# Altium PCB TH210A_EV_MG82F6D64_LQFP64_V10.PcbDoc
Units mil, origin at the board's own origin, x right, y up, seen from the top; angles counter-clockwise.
Board outline 3110.24 x 2110 mil, 2 copper layers (Top Layer, Bottom Layer); 48 components, 79 nets, 337 pads, 187 vias.
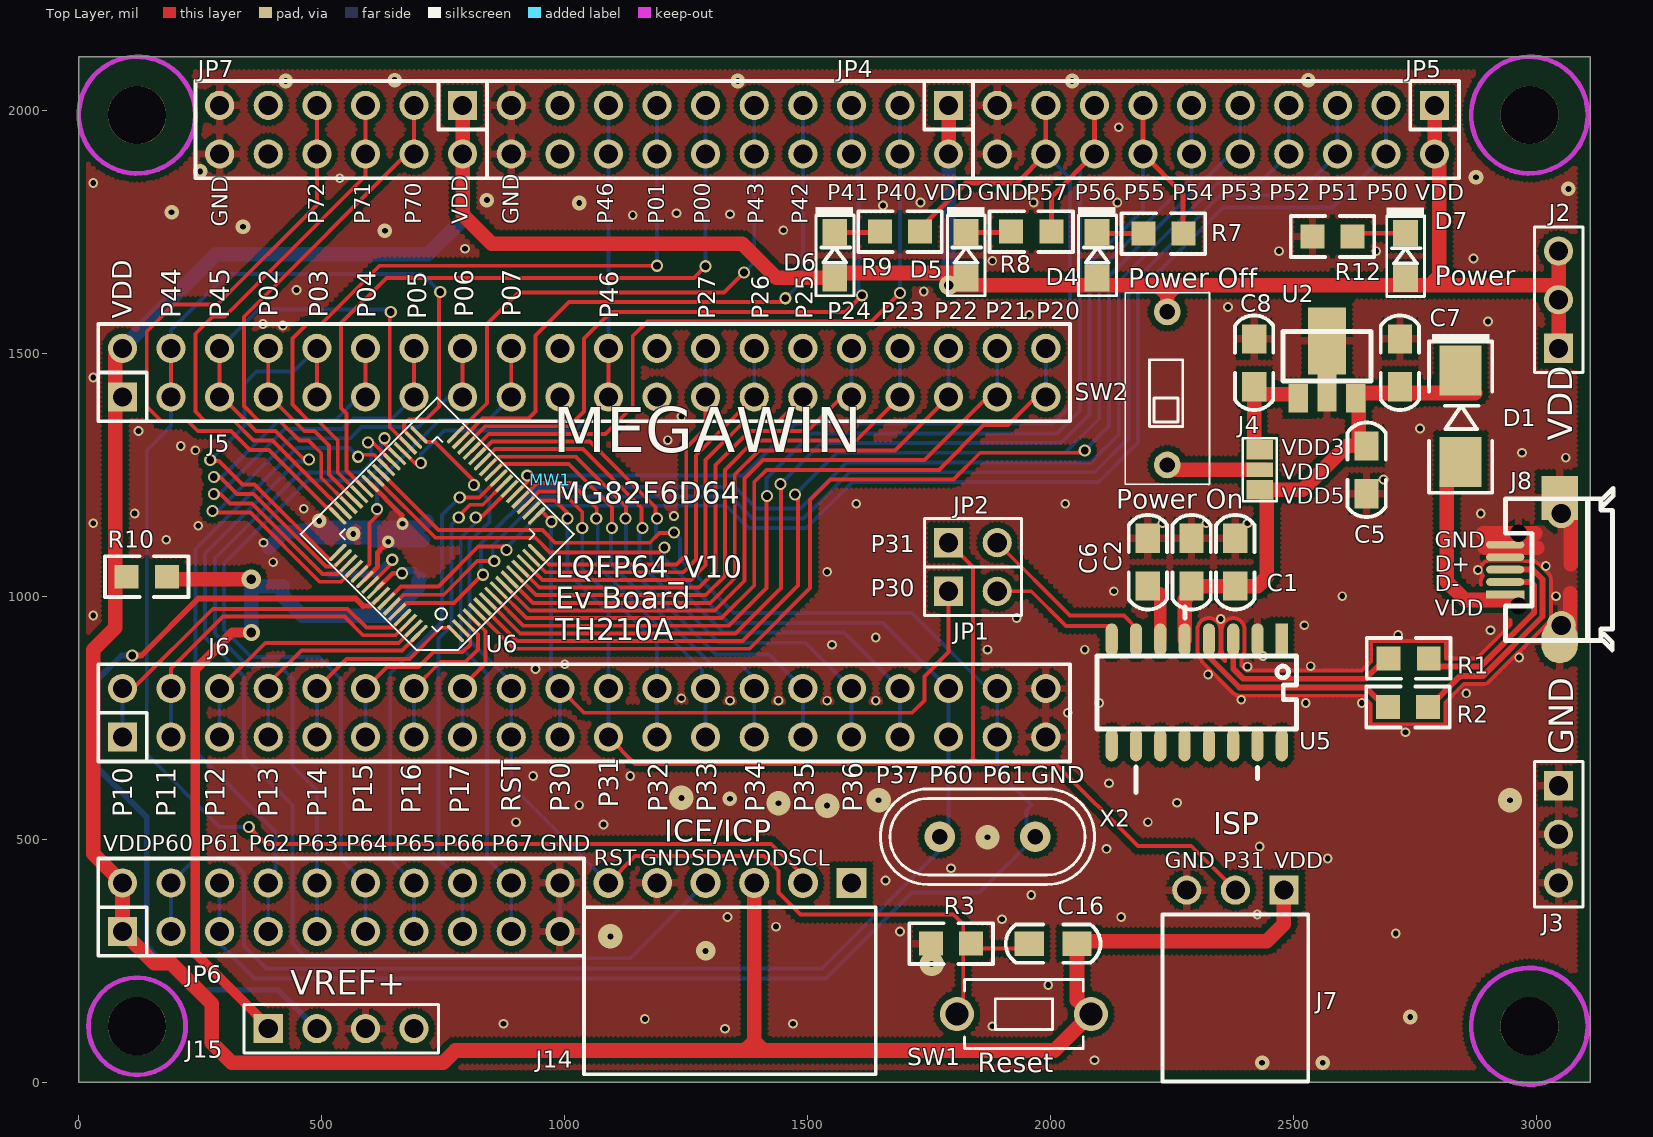
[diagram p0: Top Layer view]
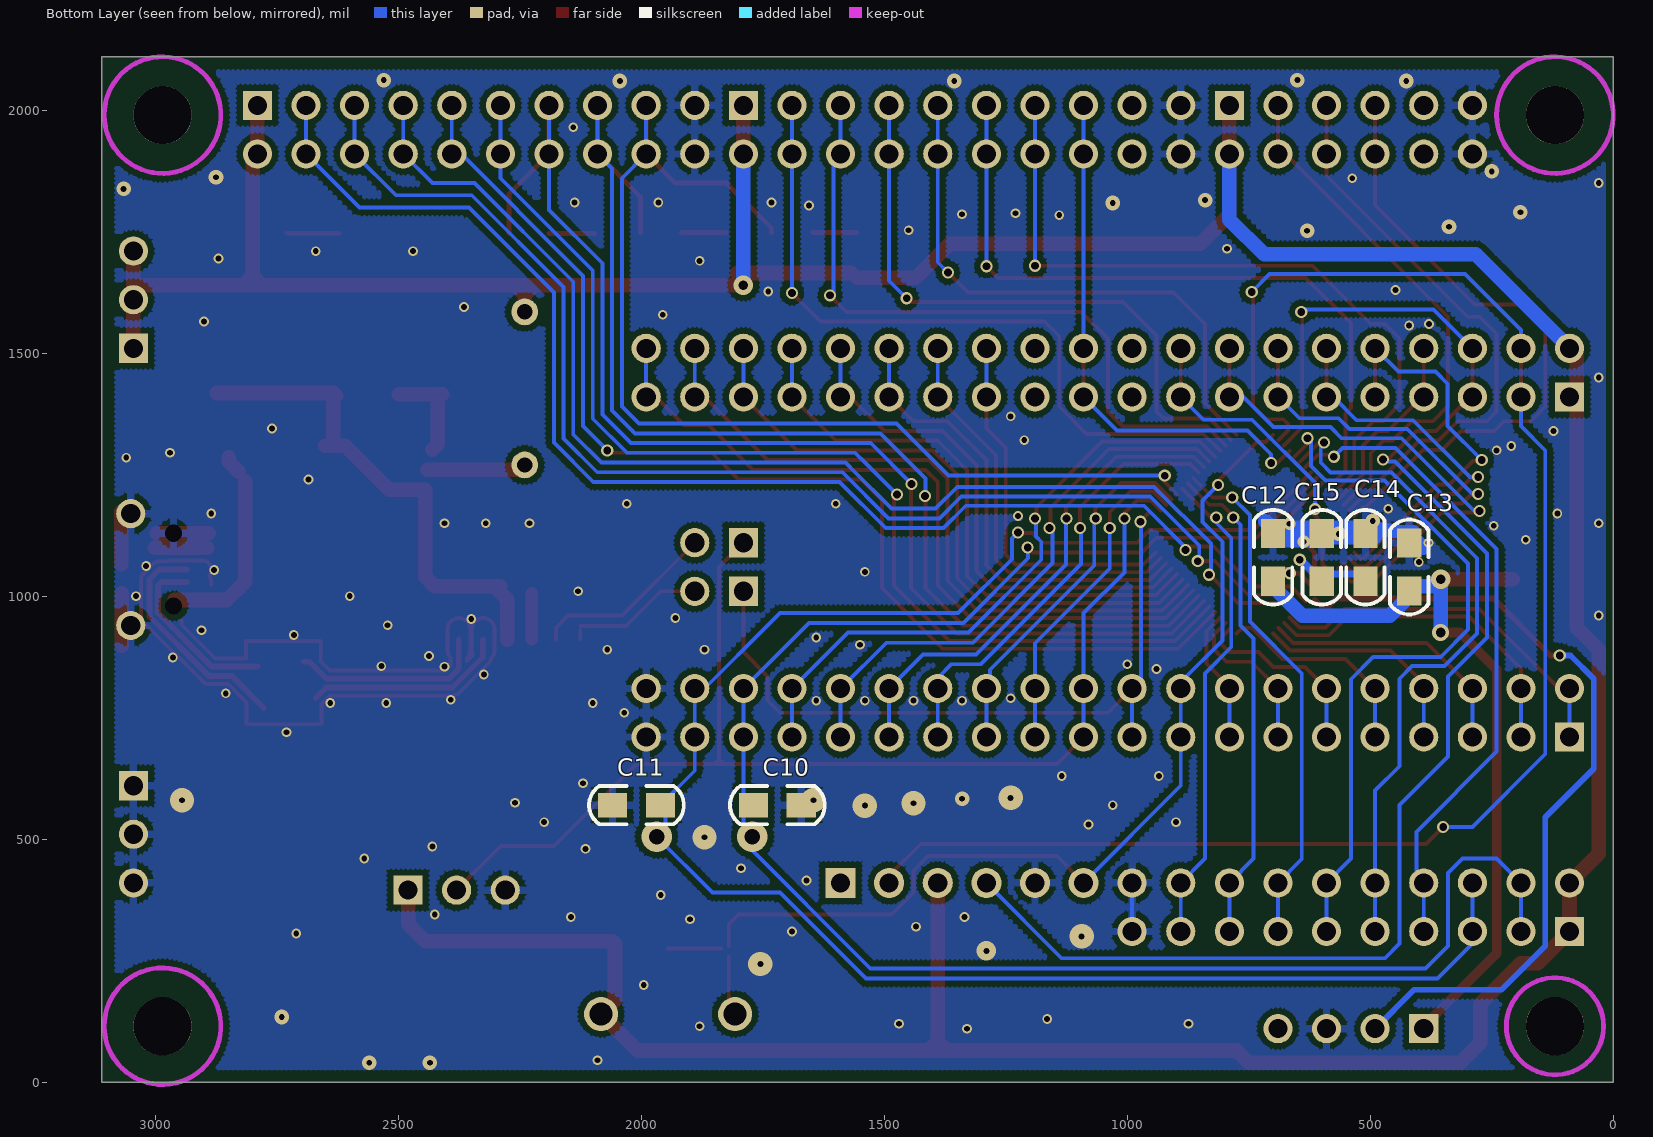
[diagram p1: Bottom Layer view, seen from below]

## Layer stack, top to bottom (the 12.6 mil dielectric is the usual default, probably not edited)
Top Layer: signal copper 1.4
Dielectric: dielectric 12.6, FR-4, Dk 4.8
Bottom Layer: signal copper 1.4

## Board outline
0,0 0,2110 3110.24,2110 3110.24,0

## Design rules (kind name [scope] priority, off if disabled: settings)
Clearance 12 [All] p1 off: gap=12
Clearance 7 [All] p2 off: gap=7
Clearance 6 [All] p3: gap=6
ComponentClearance [All] p1 off: gap=10 collisioncheckmode=3 verticalgap=10 showdistances=FALSE
HoleSize [All] p1: absolutevalues=TRUE maxlimit=500 minlimit=1 maxpercent=80.000 minpercent=20.000
MinimumSolderMaskSliver [All] p1 off: minsoldermaskwidth=10
PolygonConnect VIA [ISVIA] p1: connectstyle=Direct reliefconductorwidth=10 reliefentries=4 polygonreliefangle="90 Angle"
PolygonConnect [All] p2: connectstyle=Relief reliefconductorwidth=15 reliefentries=4 polygonreliefangle="90 Angle"
RoomDefinition TH210A_EV_MG82F6D64_LQFP64_V10 [InComponentClass('TH210A_EV_MG82F6D64_LQFP64_V10')] p1: confinementstyle=ConfineIn formatcopy=TRUE lockcomponents=FALSE outline -390,-330 3340,-330 3340,2230 -390,2230
RoutingVias [All] p1: holewidth=16 width=25 viastyle="Through Hole" minholewidth=16 minwidth=24 maxholewidth=28 maxwidth=50
SilkToSilkClearance [All] p1 off: silktosilkclearance=10
SilkscreenOverComponentPads [All] p1 off: minsilkscreentomaskgap=10
SolderMaskExpansion [All] p1 off: expansion=4
Width [All] p1: maxlimit=200 minlimit=6 preferedwidth=10
23 further rules are at their usual default settings.

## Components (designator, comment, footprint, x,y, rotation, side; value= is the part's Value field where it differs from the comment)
C1 "4.7uF" 0805C 2380,1070 r90 top
C2 "0.1uF" 0805C 2290,1070 r270 top
C5 "4.7uF" 0805C 2650,1260 r270 top
C6 "1uF" 0805C 2200,1070 r270 top
C7 "0.1uF" 0805C 2718.66,1480.28 r90 top
C8 "4.7uF" 0805C 2418.66,1480.28 r90 top
C10 "NC" 0805C 1720,570 r0 bottom
C11 "NC" 0805C 2010,570 r180 bottom
C12 "0.1uF" 0805C 700,1080 r90 bottom
C13 "4.7uF" 0805C 420,1060 r90 bottom
C14 "0.1uF" 0805C 510,1080 r90 bottom
C15 "4.7uF" 0805C 600,1080 r90 bottom
C16 "4.7uF" 0805C 2005,285 r180 top
D1 "1N5817" D5817_SMD_1 2843.66,1370.28 r270 top
D4 "Green" 0805D 2095.71,1701.71 r90 top
D5 "Red" 0805D 1825.71,1701.71 r90 top
D6 "Green" 0805D 1555.71,1701.71 r90 top
D7 "Yellow" 0805D 2730,1700 r90 top
J2 "*" PS3P254 3045.24,1510 r90 top
J3 "*" PS3P254 3045.24,610 r270 top
J4 "*" JUMP3_SMD 2430,1260 r90 top
J5 "CON40A" PS20X2P254 90,1410 r0 top locked
J6 "CON40A" PS20X2P254 90,710 r0 top locked
J7 "*" PS3P254f_90 2480,395 r180 top
J8 "Micro USB" JACK_USB_SMD290X220P065 2935.24,1054.72 r180 top
J14 "CON6" PS6P254F_90 1590,410 r180 top locked
J15 "CON4" PS4P254 390,110 r0 top
JP1 "JUMPER2" PS2P254 1790,1010 r0 top
JP2 "JUMPER2" PS2P254 1790,1110 r0 top
JP4 "CON20A" PS10X2P254 1790,2010 r180 top locked
JP5 "CON20A" PS10X2P254 2790,2010 r180 top locked
JP6 "CON20A" PS10X2P254 90,310 r0 top locked
JP7 "CON12A" PS6X2P254 790,2010 r180 top locked
MW1 "MW-A4" MEGAWIN_T 970,1240 r0 top
R1 "22" 0805R 2736.58,872 r180 top
R2 "22" 0805R 2735.24,772 r180 top
R3 "47K" 0805R 1795,285 r0 top
R7 "1K" 0805R 2231.97,1745.97 r180 top
R8 "1K" 0805R 1960,1750 r180 top
R9 "1K" 0805R 1690,1750 r180 top
R10 "10" 0805R 140,1040 r0 top
R12 "1K" 0805R 2580,1740 r0 top
SW1 "SW TACT-SPST" SW_T_2P 1945,140 r180 top
SW2 "-" DIP2_SW 2240,1270 r90 top
U2 "AIC1734-33(SOT-89)" SOT89 2568.66,1407.17 r0 top
U5 "MA111AS16" SO16_150P127 2300.63,802 r270 top
U6 "MG82F6D64_LQFP64" QFP64_7X7P040 737.58,1127.62 r135 top locked
X2 "NC" X49U 1870,505 r180 top

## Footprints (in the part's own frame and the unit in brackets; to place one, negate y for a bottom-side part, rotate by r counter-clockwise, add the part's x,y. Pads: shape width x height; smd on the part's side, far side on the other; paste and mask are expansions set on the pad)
0805C [mil]
  rect 60x50 smd: 1(-49.21,0) 2(49.21,0)
  silkscreen extent -97,-39 97,39
0805D [mm]
  rect 1.4x1.3 smd: 1(-1.192,0) 2(1.192,0)
  silkscreen extent -2.12,-1 2.53,1
0805R [mm]
  rect 1.25x1.25 smd: 1(-1.05,0) 2(1.05,0)
  silkscreen extent -2.18,-1.07 2.18,1.07
D5817_SMD_1 [mm]
  rect 2.6x2.2 smd: 1(2.39,0) 2(-2.39,0)
  silkscreen extent -4.29,-1.65 4,1.65
DIP2_SW [mm]
  round 1.4 hole 0.8: 1(0,0) 2(8,0)
  silkscreen extent -1.02,-2.2 9.02,2.2
JACK_USB_SMD290X220P065 [mm]
  rect 1.9x1.8 on Mech2: 0(-2.85,-1.15) 0(-2.85,1.15)
  round 0.8 hole 0.9 unplated: 1(-0.7,1.9) 6(-0.7,-1.9)
  rect 2x0.4 smd: 1(0,1.3)
  oval 2x0.4 smd: 2(0,0.65) 3(0,0) 4(0,-0.65) 5(0,-1.3)
  round 1.524 hole 1: 5(-2.931,2.921) 5(-2.931,-2.921)
  oval 1.9x2.3 smd: 5(-2.85,3.75)
  rect 1.9x2.3 smd: 5(-2.85,-3.75)
  silkscreen extent -5.65,-4.25 -0.01,4.2
JUMP3_SMD [mil]
  rect 40x55 smd: 1(-41,0) 3(41,0)
  rect 30x55 smd: 2(0,0)
  silkscreen extent -65,-35 65,35
MEGAWIN_T [mil]
PS2P254 [mil]
  rect 60x60 hole 39.37: 1(0,0)
  round 60 hole 39.37: 2(100,0)
  silkscreen extent -50,-50 150,50
PS3P254 [mil]
  rect 60x60 hole 39.37: 1(0,0)
  round 60 hole 39.37: 2(100,0) 3(200,0)
  silkscreen extent -50,-50 250,50
PS3P254f_90 [mil]
  rect 60x60 hole 39.37: 1(0,0)
  round 60 hole 39.37: 2(100,0) 3(200,0)
  silkscreen extent -50,50 250,394
PS4P254 [mil]
  rect 60x60 hole 39.37: 1(0,0)
  round 60 hole 39.37: 2(100,0) 3(200,0) 4(300,0)
  silkscreen extent -50,-50 350,50
PS6P254F_90 [mil]
  rect 62x62 hole 39.37: 1(0,0)
  round 62 hole 39.37: 2(100,0) 3(200,0) 4(300,0) 5(400,0) 6(500,0)
  silkscreen extent -50,50 550,394
PS6X2P254 [mil]
  rect 60x60 hole 39.37: 1(0,0)
  round 60 hole 39.37: 2(0,100) 3(100,0) 4(100,100) 5(200,0) 6(200,100) 7(300,0) 8(300,100) 9(400,0) 10(400,100) 11(500,0) 12(500,100)
  silkscreen extent -50,-50 550,150
PS10X2P254 [mil]
  rect 60x60 hole 39.37: 1(0,0)
  round 60 hole 39.37: 2(0,100) 3(100,0) 4(100,100) 5(200,0) 6(200,100) 7(300,0) 8(300,100) 9(400,0) 10(400,100) 11(500,0) 12(500,100) 13(600,0) 14(600,100) 15(700,0) 16(700,100) 17(800,0) 18(800,100) 19(900,0) 20(900,100)
  silkscreen extent -50,-50 950,150
PS20X2P254 [mil]
  rect 60x60 hole 39.37: 1(0,0)
  round 60 hole 39.37: 2(0,100) 3(100,0) 4(100,100) 5(200,0) 6(200,100) 7(300,0) 8(300,100) 9(400,0) 10(400,100) 11(500,0) 12(500,100) 13(600,0) 14(600,100) 15(700,0) 16(700,100) 17(800,0) 18(800,100) 19(900,0) 20(900,100) 21(1000,0) 22(1000,100) 23(1100,0) 24(1100,100) 25(1200,0) 26(1200,100) 27(1300,0) 28(1300,100) 29(1400,0) 30(1400,100) 31(1500,0) 32(1500,100) 33(1600,0) 34(1600,100) 35(1700,0) 36(1700,100) 37(1800,0) 38(1800,100) 39(1900,0) 40(1900,100)
  silkscreen extent -50,-50 1950,150
QFP64_7X7P040 [mm]
  oval 1.2x0.19 smd: 1(-4.35,3) 12(-4.35,-1.4) 16(-4.35,-3) 33(4.35,-3) 34(4.35,-2.6) 38(4.35,-1) 41(4.35,0.2) 42(4.35,0.6) 48(4.35,3)
  rect 1.2x0.19 smd: 2(-4.35,2.6) 3(-4.35,2.2) 4(-4.35,1.8) 5(-4.35,1.4) 6(-4.35,1) 7(-4.35,0.6) 8(-4.35,0.2) 9(-4.35,-0.2) 10(-4.35,-0.6) 11(-4.35,-1) 13(-4.35,-1.8) 14(-4.35,-2.2) 15(-4.35,-2.6) 35(4.35,-2.2) 36(4.35,-1.8) 37(4.35,-1.4) 39(4.35,-0.6) 40(4.35,-0.2) 43(4.35,1) 44(4.35,1.4) 45(4.35,1.8) 46(4.35,2.2) 47(4.35,2.6)
  oval 0.19x1.2 smd: 17(-3,-4.35) 24(-0.2,-4.35) 27(1,-4.35) 32(3,-4.35) 49(3,4.35) 50(2.6,4.35) 53(1.4,4.35) 54(1,4.35) 61(-1.8,4.35) 64(-3,4.35)
  rect 0.19x1.2 smd: 18(-2.6,-4.35) 19(-2.2,-4.35) 20(-1.8,-4.35) 21(-1.4,-4.35) 22(-1,-4.35) 23(-0.6,-4.35) 25(0.2,-4.35) 26(0.6,-4.35) 28(1.4,-4.35) 29(1.8,-4.35) 30(2.2,-4.35) 31(2.6,-4.35) 51(2.2,4.35) 52(1.8,4.35) 55(0.6,4.35) 56(0.2,4.35) 57(-0.2,4.35) 58(-0.6,4.35) 59(-1,4.35) 60(-1.4,4.35) 62(-2.2,4.35) 63(-2.6,4.35)
  silkscreen extent -5.05,-5.05 5.05,5.05
SO16_150P127 [mil]
  rect 67x25 smd: 1(-108.5,175)
  oval 67x25 smd: 2(-108.5,125) 3(-108.5,75) 4(-108.5,25) 5(-108.5,-25) 6(-108.5,-75) 7(-108.5,-125) 8(-108.5,-175) 9(108.5,-175) 10(108.5,-125) 11(108.5,-75) 12(108.5,-25) 13(108.5,25) 14(108.5,75) 15(108.5,125) 16(108.5,175)
  silkscreen extent -176,-205 206,205
SOT89 [mm]
  rect 1.016x1.5 smd: 1(-1.5,0) 3(1.5,0)
  rect 1.016x2.6 smd: 2(0,0.6)
  rect 2x3.5 smd: 2(0,3)
  silkscreen extent -2.3,0.9 2.3,3.5
SW_T_2P [mil]
  round 70 hole 47.24: 1(-137.79,0) 2(137.79,0)
  silkscreen extent -122,-71 122,71
X49U [mm]
  round 1.6 hole 0.8: 1(-2.5,0) 2(2.5,0)
  silkscreen extent -5.6,-2.5 5.6,2.5

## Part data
C1 C5 C8: library part CAP
C2 C6 C7 C12 C13 C14 C15: library part "CAP NP"
C10 C11: library part "C NP"
C16: library part C
D1: library part DIODE_ZD, "Schottky Diode"
D4 D5 D6 D7: library part LED
J2 J3 J4 J7: library part CON3
J8: library part CON6
JP7: library part CON12A_0
MW1: library part MW_A4_1
R1 R2 R3 R10: library part R
R7 R8 R9 R12: library part R_Dup2
SW2: library part SW-2
U2: library part AIC1734-33(SOT-89)_0
U6: library part FA245_LQFP64_0
X2: library part CRYSTAL

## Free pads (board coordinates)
  round 120 hole 120 unplated: 0(120,115) 0(120,1990) 0(2985.24,115) 0(2985.24,1990)

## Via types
v1: diameter 20, hole 12, Top Layer to Bottom Layer, tented both sides, 110 vias
v2: diameter 25, hole 16, Top Layer to Bottom Layer, tented both sides, 44 vias
v3: diameter 30, hole 12, Top Layer to Bottom Layer, tented both sides, 19 vias
v4: diameter 50, hole 12, Top Layer to Bottom Layer, tented both sides, 8 vias
v5: diameter 25, hole 12, Top Layer to Bottom Layer, tented both sides, 2 vias
v6: diameter 40, hole 20, Top Layer to Bottom Layer, tented both sides, 2 vias
v7: diameter 40, hole 12, Top Layer to Bottom Layer, tented both sides, 1 vias
v8: diameter 35, hole 20, Top Layer to Bottom Layer, tented both sides, 1 vias

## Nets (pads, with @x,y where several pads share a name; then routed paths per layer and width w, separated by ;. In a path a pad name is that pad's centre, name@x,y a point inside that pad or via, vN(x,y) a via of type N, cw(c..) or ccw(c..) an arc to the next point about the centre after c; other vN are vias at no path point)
CHIP_VDD: C12.1 C13.1 J15.1 R10.2 U6.56 | length 1696.8
  Top Layer w10: U6.56@616.92,1018.08 645.83,1047 v2(665,1047)
  Top Layer w20: v8(355,925) 315.8,925 240,849.2 240,265 380,125 J15.1@390,125
  Top Layer w30: 207,1035 v6(355,1035) v6@360,1035
  Bottom Layer w15: v2@666,1052 C12.1@692,1052
  Bottom Layer w30: v8(355,925) v6@355,1020 ; v6@355,1030.34 v6@355,1020 ; C13.1@420,1010 420,1000 460,960 640,960 698.22,1018.22 698.22,1032.57 C12.1@702.15,1036.51 ; C13.1@420,1020 v6@355,1020
D+: R2.2 U5.4 | length 414.9
  Top Layer w12: U5.4 2325.63,875 2388.63,812 2648.5,812 R2.2@2670,790.5
D-: R1.2 U5.3 | length 402.4
  Top Layer w12: U5.3 2375.63,850.46 2396.09,830 2648.03,830 2683.03,865 R1.2@2695,865
GND_POWER: C1.2 C2.1 C5.2 C6.1 C7.2 C8.2 C10.1 C11.1 C12.2 C13.2 C14.2 C15.2 J3.1 J3.2 J3.3 J6.39 J6.40 J7.3 J8.4 J8.5 J8.6 J14.5 J15.3 JP4.19 JP4.20 JP5.19 JP5.20 JP6.19 JP6.20 JP7.11 JP7.12 R3.1 R12.1 U2.2 U5.2 U6.42 U6.54 | length 3669.6
  Top Layer w8: 2313.61,862.98 cw(c2325.63,875) 2308.73,873.17 ; 2657.98,778.48 2641.46,795 v1@2388.63,795 ; 2658.29,778.18 2658.29,736.39 2812.18,736.39 2812.18,781.19 2849.99,819 2890.24,819 ; 2885.54,1024.15 cw(c2903.74,1029.13) 2889.87,1041.93 cw(c2903.74,1054.72) 2903.74,1073.6 2966.73,1073.6 cw(c2966.73,1054.72) 2974.93,1071.72 2990.17,1071.72 ; 2902.26,823.98 cw(c2890.24,836) 2890.24,819 ; 2945.87,949.61 2945.87,941.13 2876.74,872 2813.52,872 2813.52,907.61 2659.63,907.61 2659.63,865.64 2640.99,847 2403.13,847 2392.63,857.5 2392.63,873.28 ccw(c2375.63,889.5) 2399.13,889.5 2399.13,931.5 ccw(c2375.63,931.5) 2352.13,931.5 2352.13,889.5 ccw(c2375.63,889.5) 2358.63,873.28 2358.63,866.04 2346.32,878.35 ccw(c2325.63,889.5) 2349.13,889.5 2349.13,931.5 ccw(c2325.63,931.5) 2302.13,931.5 2302.13,889.5 ccw(c2325.63,889.5) 2308.73,873.17 ; 2991.17,1071.69 cw(c2992.17,1054.72) 3004.19,1066.75 3024.24,1046.69 cw(c3012.24,1034.65) 3029.24,1034.65 ; 3024.26,1046.67 cw(c3012.24,1034.65) 3029.24,1034.65 ; 2308.73,873.17 ccw(c2325.63,875) 2313.63,862.96 2376.59,800 ; 2376.59,800 ccw(c2388.63,812) v1@2388.63,795 ; 2376.61,799.98 ccw(c2388.63,812) v1@2388.63,795 ; 2890.24,819 ccw(c2890.24,836) 2902.28,824 3024.24,945.96 ccw(c3012.24,958) 3029.24,958 3029.24,1034.65
  Top Layer w10: U6.54 615,1060.71 615,1090 v5(637,1112) ; U6.42 665,1166.79 v5@665,1146
  Top Layer w30: 2889.72,1129.53 J8.6 2997.51,1129.53 ; 2893.44,1100 3001.24,1100 ; J8.5@3069.24,898 3069.24,1005.8 ; 3070.24,1066.2 J8.5@3070.24,1174
  Bottom Layer w8: JP6.19 JP6.20
  Bottom Layer w10: C15.2@611,1115.01 C15.2@611,1135.68
  Bottom Layer w30: 390.67,1099.33 C13.2@411.34,1120 ; C13.2@411,1131 425,1131 496.83,1139.45 507.72,1140.73 508.63,1140.84 510,1141 700,1141 C12.2@716,1154 ; C14.2@491.34,1121.34 C15.2@600,1121.34 ; C15.2@608,1115.01 611,1115.01 C12.2@708,1115.01
  other v1: 2090,45 1330,110 1880,115 874,120 1470,120 1165,130 1995,200 2710,306 1690,310 1435,320 1900,335 1335,340 2145,340 2425,345 1960,385 1660,415 1795,440 2570,460 2115,480 2430,485 1080,530 900,535 2200,535 1030,570 2260,575 2120,615 935,630 1135,630 2730,720 2035,760 2100,780 2525,780 2640,780 1340,785 1440,785 1540,785 1640,785 2392,787 1240,790 2855,800 2324,839 940,850 2405,855 2535,856 1000,860 2964,874 2437,877 1870,890 2070,890 1550,900 1640,915 2715,920 2905,930 2522,940 2350,953 1930,955 30,960 2600,1000 3040,1000 2130,1010 1540,1050 2879,1054 3019,1062 400,1070 380,1110 180,1116 246,1145 30,1150 2230,1150 2320,1150 2405,1150 1225,1165 115,1170 2885,1170 463,1180 1600,1190 2030,1190 2685,1240 3060,1285 2970,1295 240,1300 210,1309 1212,1321 123,1340 2760,1345 1240,1370 30,1450 420,1557 379,1560 2900,1565 1956,1579 2365,1595 1739,1627 448,1630 1880,1690 2870,1695 2470,1710 2670,1710 795,1715 1450,1753 1140,1784 1340,1786 1230,1788 1655,1804 1732,1810 1965,1810 2137.24,1810 30,1850 537,1860 2140,1965
  other v3: 2435,40 2560,40 2740,134 1340,583 565,1128 495,1155 630,1752 338,1760 191,1790 1030,1809 840,1815 3065.24,1838 2875.24,1862 250,1874 426,2060 1356,2060 2044,2060 650,2062 2530,2062
  other v4: 1755,243 1094,300 1870,504 1540,569 1440,574 1646,580 2945.24,580 1240,585
  other v5: 666,1149
  other v7: 1290,270
MA111_RX: JP2.2 U5.7 | length 382.6
  Top Layer w8: JP2.2 2040,960 2150.63,960 2175.63,935 U5.7
MA111_TX: JP1.2 U5.8 | length 284.6
  Top Layer w8: JP1.2 1960,1010 2031.21,938.79 U5.8@2125.63,938.79 ; U5.8 U5.8@2125.63,930
NetC6_2: C6.2 U5.6 | length 95.8
  Top Layer w25: U5.6 2225.63,1006.34
NetC14_1: C14.1 C15.1 U6.55 | length 190
  Top Layer w8: U6.55 v2@643,1066.44
  Bottom Layer w15: C14.1@515,1045.5 C15.1@600,1045.5 ; C15.1@612,1044 v2@643,1075
  other v2: 645,1075
NetD1_1: D1.1 J8.1 | length 404.9
  Top Layer w30: D1.1@2815,1235.91 2815,1030 2852.91,992.09 J8.1@2960,992.09 ; D1.1@2828.66,1256.19 2848.66,1276.19 D1.1@2848.66,1286.19
NetD4_2: D4.2 R7.2 | length 94.9
  Top Layer w10: D4.2@2095.71,1745.97 R7.2
NetD5_2: D5.2 R8.2 | length 91.7
  Top Layer w10: D5.2 R8.2@1917.45,1748.63
NetD6_2: D6.2 R9.2 | length 91.7
  Top Layer w10: D6.2 R9.2@1647.45,1748.63
NetD7_2: D7.2 R12.2 | length 108.7
  Top Layer w10: R12.2@2621.34,1746.92 D7.2
NetJ4_2: J4.2 SW2.1 | length 200
  Top Layer w30: SW2.1@2240,1260 J4.2 J4.2@2440,1260
NetJ8_2: J8.2 R1.1 | length 366.8
  Top Layer w12: R1.1@2790,855 2883.78,855 2994.24,965.46 2994.24,1022.57 2987.67,1029.13 ; J8.2 2985.67,1029.13
NetJ8_3: J8.3 R2.1 | length 473.1
  Top Layer w12: R2.1@2776.95,770 2842.95,836 2890.24,836 3012.24,958 3012.24,1034.65 2992.17,1054.72 ; J8.3 2990.17,1054.72
P00: JP4.11 JP4.12 U6.43 | length 1490.7
  Top Layer w8: U6.43 551,1258.52 551,1376 540,1387 540,1562 633,1655 1266,1655 v2(1290,1679)
  Bottom Layer w8: v2(1290,1679) JP4.12 JP4.11
P01: JP4.13 JP4.14 U6.44 | length 1530.5
  Top Layer w8: U6.44 533,1254.25 533,1320 493,1360 474,1360 440,1394 440,1530 470,1560 499,1560 619,1680 v2(1190,1680)
  Bottom Layer w8: v2(1190,1680) JP4.14 JP4.13
P02: J5.7 J5.8 U6.45 | length 417.9
  Top Layer w8: J5.8 390,1412 391,1411 393,1411 464,1340 485,1340 515,1310 515,1249.98 U6.45
  Bottom Layer w8: J5.7@370,1410 J5.7
P03: J5.9 J5.10 U6.49 | length 816.5
  Top Layer w8: v2@270.65,1278.45 288.55,1278.45 337,1230 362,1230 515.01,1076.99 519.93,1076.99 U6.49 ; J5.9 J5.10
  Bottom Layer w8: v2(270.65,1280) 340.83,1350.17 ; 341,1350.17 341,1437 366,1462 442,1462 J5.10
P04: J5.11 J5.12 U6.50 | length 829.9
  Top Layer w8: v2(278,1245) 291,1245 326,1210 359.73,1210 508.48,1061.24 526.45,1061.24 U6.50 ; J5.11 J5.12
  Bottom Layer w8: v2(278,1245) 295,1245 412,1362 528,1362 576,1410 J5.11
P05: J5.13 J5.14 U6.51 | length 949.4
  Top Layer w8: v2(278,1210) 292,1210 311,1191 356.46,1191 501.96,1045.5 532.97,1045.5 U6.51 ; J5.13 J5.14
  Bottom Layer w8: v2(278,1210) 290,1210 424,1344 543,1344 565,1366 646,1366 J5.13
P06: J5.15 J5.16 U6.52 | length 1066.2
  Top Layer w8: v2@279,1172 353.19,1172 495.44,1029.75 539.5,1029.75 U6.52 ; J5.15 J5.16
  Bottom Layer w8: v2@279,1174 285,1174 436,1325 559,1325 582,1348 699,1348 761,1410 J5.15
  other v2: 275,1175
P07: J5.17 J5.18 U6.53 | length 648.9
  Top Layer w8: U6.53 598,1065.98 598,1150 620,1172 v2@617,1172 ; J5.17@890,1427.01 J5.18
  Bottom Layer w8: v2(614,1179) 614,1234 743,1363 843,1363 J5.17 ; v2@617,1172 v2@619,1174 ; J5.17@881.49,1418.51 J5.17@890,1427.01
P10: J6.1 J6.2 U6.61 | length 769.1
  Top Layer w8: J6.2 112,810 275.75,973.75 553.25,973.75 591.76,935.24 645.43,935.24 U6.61
  Bottom Layer w8: J6.1 J6.2
P11: J6.3 J6.4 U6.62 | length 699.7
  Top Layer w8: J6.4 190,851 297,958 546.73,958 585.23,919.5 651.95,919.5 U6.62
  Bottom Layer w8: J6.3 J6.4
P12: J6.5 J6.6 U6.63 | length 550.3
  Top Layer w8: J6.6 383.75,903.75 658.48,903.75 U6.63
  Bottom Layer w8: J6.5 J6.6
P13: J6.7 J6.8 U6.64 | length 512.7
  Top Layer w8: J6.8 390,820 458,888 625,888 ; 575,888 625,888 ; U6.64 665,888 625,888
  Bottom Layer w8: J6.7 J6.8
P14: J6.9 J6.10 U6.1 | length 441.9
  Top Layer w8: J6.10 551,871 681,871 745,935 763.16,935 U6.1
  Bottom Layer w8: J6.9 J6.10
P15: J6.11 J6.12 U6.2 | length 423.1
  Top Layer w8: J6.12@610,830 J6.12 634,854 699,854 730,885 790,885 805.75,900.75 805.75,914.69 U6.2
  Bottom Layer w8: J6.11 J6.12
P16: J6.13 J6.14 U6.3 | length 329.9
  Top Layer w8: J6.14@689.71,810 J6.14 745,865 796,865 821.5,890.5 821.5,921.21 U6.3
  Bottom Layer w8: J6.13 J6.14
P17: J6.15 J6.16 U6.4 | length 324.3
  Top Layer w8: J6.16 790,814 837.24,861.24 837.24,927.73 ; U6.4 837.24,927.73 ; 837.24,881.24 837.24,927.73
  Bottom Layer w8: J6.15 J6.16
P20: J5.39 J5.40 U6.9 | length 1563
  Top Layer w8: U6.9 921.57,954.76 1323.01,954.76 1390,1021.76 1390,1235 1415,1260 1770,1260 1862,1352 1912,1352 1970,1410 J5.39
  Bottom Layer w8: J5.39 J5.40
P21: J5.37 J5.38 U6.10 | length 1441.7
  Top Layer w8: U6.10 928.09,970.51 1308.76,970.51 1370,1031.76 1370,1242.01 1407.99,1280 1740,1280 1870,1410 J5.37
  Bottom Layer w8: J5.37 J5.38
P22: J5.35 J5.36 U6.11 | length 1323.8
  Top Layer w8: U6.11 934.62,986.26 1299.5,986.26 1350,1036.76 1350,1250 1400,1300 1680,1300 J5.35
  Bottom Layer w8: J5.35 J5.36
P23: J5.33 J5.34 U6.12 | length 1207.2
  Top Layer w8: U6.12 941.14,1002.01 1290.25,1002.01 1330,1041.76 1330,1260 1390,1320 1600,1320 J5.33
  Bottom Layer w8: J5.33 J5.34
P24: J5.31 J5.32 U6.13 | length 1087.6
  Top Layer w8: U6.13 947.66,1017.76 1276,1017.76 1310,1051.76 1310,1270 1380,1340 1500,1340 1570,1410 J5.31
  Bottom Layer w8: J5.31 J5.32
P25: J5.29 J5.30 U6.14 | length 969
  Top Layer w8: U6.14 954.18,1033.5 1260,1033.5 1290,1063.5 1290,1280 1370,1360 1440,1360 J5.29 J5.29@1490,1412.01
  Bottom Layer w8: J5.29 J5.30
P26: J5.27 J5.28 U6.15 | length 846.5
  Top Layer w8: U6.15 960.71,1049.25 1244.15,1049.25 1270,1075.11 1270,1290 J5.27
  Bottom Layer w8: J5.27 J5.28
P27: J5.25 J5.26 U6.16 | length 768
  Top Layer w8: U6.16 967.23,1065 1230,1065 1250,1085 1250,1305 1290,1345 J5.25
  Bottom Layer w8: J5.25 J5.26
P30/RXD: J6.19 J6.20 JP1.1 U6.17 | length 1499.5
  Top Layer w8: U6.17@954,1173 v2@969.76,1157.24 ; v2@972,1152 v2@972,1153 ; J6.20 1040,760 1715,760 1740,785 1740,835 1790,885 JP1.1
  Bottom Layer w8: v2@972,1152 972,828 J6.20 J6.19
  other v2: 973,1153
P31/TXD: J6.21 J6.22 J7.2 JP2.1 U6.18 | length 2514.5
  Top Layer w8: U6.18 951.73,1197 980,1197 1006,1171 v2(1006,1160) ; J6.21 1145,655 1830,655 ; JP2.1 1840,1060 1840,665 ; J7.2 2289.33,485.67 2179.33,485.67 2010,655 1850,655 ; 1830,655 1840,655 ; 1830,655 1840,665 ; 1840,655 1850,655 ; 1840,655 1840,665 ; 1840,665 1850,655
  Bottom Layer w8: v2(1006,1160) 1006,1049 1090,965 J6.22 J6.21
P32: J6.23 J6.24 U6.19 | length 671.7
  Top Layer w8: U6.19 947.46,1215 994,1215 1036,1173 v2(1036,1140)
  Bottom Layer w8: v2(1036,1140) 1036,1057 1190,903 J6.24 J6.23
P33: J6.25 J6.26 U6.20 | length 746
  Top Layer w8: U6.20 943.19,1233 1013,1233 1066,1180 v2@1066,1165
  Bottom Layer w8: v2@1064,1154 1068,1150 1068,1063 1282.5,848.5 1282.5,802.5 1290,795 J6.25
  other v2: 1065,1160
P34: J6.27 J6.28 U6.25 | length 912.8
  Top Layer w8: U6.25 870.59,1271.76 1008.24,1271.76 1097,1183 v2(1097,1140)
  Bottom Layer w8: v2@1095,1134 1095,1066 1301,860 1362,860 1390,832 J6.28 J6.27
P35: J6.29 J6.30 U6.26 | length 1024
  Top Layer w8: U6.26 863.32,1286.76 1023.24,1286.76 1126,1184 v2@1126,1154
  Bottom Layer w8: v2@1126,1154 1126,1065 1311,880 1420,880 J6.30 J6.29
  other v2: 1125,1160
P36: J6.31 J6.32 U6.27 | length 1153.2
  Top Layer w8: U6.27 856.79,1302.5 1037.5,1302.5 1158,1182 v2@1158,1134
  Bottom Layer w8: v2(1160,1140) 1154,1134 1154,1068 1317.83,904.17 1495.83,904.17 J6.32 J6.31
P37: J6.33 J6.34 U6.28 | length 1274.1
  Top Layer w8: U6.28 850.27,1318.25 1051.75,1318.25 1187,1183 v2@1187,1154
  Bottom Layer w8: v2@1186,1154 v2@1188,1152 ; v2@1188,1154 v2@1188,1152 ; J6.33 J6.34 1575,925 1327,925 1177,1075 1177,1112 1188,1123 v2@1188,1152
  other v2: 1190,1160
P40: JP4.3 JP4.4 U6.29 | length 1487.1
  Top Layer w8: U6.29 843.75,1334 1084,1334 1140,1390 1140,1535 1170,1565 1631,1565 v2(1690,1624)
  Bottom Layer w8: v2(1690,1624) JP4.4 JP4.3
P41: JP4.5 JP4.6 U6.30 | length 1424.2
  Top Layer w8: U6.30 837.22,1349.75 1009.75,1349.75 1040,1380 1040,1530 1095,1585 1578,1585 v2(1612,1619)
  Bottom Layer w8: JP4.6 JP4.5 ; v2@1604.76,1619 JP4.6@1604.76,1912.76
P42: JP4.7 JP4.8 U6.31 | length 1288.6
  Top Layer w8: U6.31 830.7,1365.5 925.5,1365.5 940,1380 940,1536 1009,1605 v2@1454,1605
  Bottom Layer w8: v2(1454,1613) 1490,1649 JP4.8 JP4.7
P43: JP4.9 JP4.10 U6.32 | length 1180.2
  Top Layer w8: U6.32 840,1397.07 840,1560 905,1625 1328,1625 v2(1369,1666)
  Bottom Layer w8: v2(1369,1666) 1390,1687 JP4.10 JP4.9
P46: J5.21 J5.22 JP4.15 JP4.16 U6.36 | length 1103.6
  Top Layer w8: U6.36 691.42,1274 v2(704,1274) ; J5.21 J5.22
  Bottom Layer w8: v2(704,1274) 704,1292 753,1341 1021,1341 J5.21 ; JP4.16@1077,1910 JP4.16@1077,1913 ; J5.22 JP4.16 JP4.15
P50: JP5.3 JP5.4 U6.58 | length 2840.8
  Top Layer w8: U6.58 663.37,1020 740,1020 822.01,1102.01 872.99,1102.01 v2(880,1095)
  Bottom Layer w8: v2(880,1095) 880,1100 966,1186 1332.43,1186 1378.43,1140 1497,1140 1592,1235 1675,1235 ; 1600,1235 1675,1235 ; JP5.3 JP5.4 2580,1800 2355,1800 2180,1625 2180,1316.08 2098.92,1235 1675,1235
P51: JP5.5 JP5.6 U6.59 | length 2701.1
  Top Layer w8: U6.59 668.64,1003 751,1003 820,1072 v2(855,1072)
  Bottom Layer w8: v2(855,1072) 857,1074 852,1079 852,1104.26 952.74,1205 1341.72,1205 1386.72,1160 1491,1160 1586,1255 1620,1255 ; 1595,1255 1620,1255 ; JP5.5 JP5.6 2505,1825 2349,1825 2160,1636 2160,1324.37 2090.63,1255 1620,1255
P52: JP5.7 JP5.8 U6.60 | length 2647.5
  Top Layer w8: U6.60 673.92,986 772,986 v2@834,1048
  Bottom Layer w8: v2@834,1048 828,1054 828,1108 945,1225 1350,1225 1395,1180 1485,1180 1565.17,1260.17 ; 1574,1269 1565.17,1260.17 ; 1590,1275 1635,1275 ; JP5.7 JP5.8 2430,1850 2343,1850 2140,1647 2140,1332.65 2082.35,1275 1635,1275 ; 1565.17,1260.17 1580,1275 1635,1275
  other v2: 832,1044
P53: JP5.9 JP5.10 U6.5 | length 2397.4
  Top Layer w8: U6.5 895.49,891.76 1380,891.76 1505,1016.76 1505,1198 1547,1240 1800,1240 1855,1295 v2@2070,1295
  Bottom Layer w8: v2(2070,1300) 2120.06,1350.06 2120.06,1659.06 2390,1929 JP5.9
P54: JP5.11 JP5.12 U6.6 | length 2353.2
  Top Layer w8: U6.6 902.02,907.5 1365.75,907.5 1480,1021.76 1480,1210 v2@1476.5,1213.5
  Bottom Layer w8: v2(1474,1209) 1538.98,1273.98 ; 1553,1288 1538.98,1273.98 ; JP5.11 JP5.12 2290,1860 2100,1670 2100,1365.15 2029.85,1295 1560,1295 1538.98,1273.98
P55: JP5.13 JP5.14 R7.1 U6.7 | length 2590.5
  Top Layer w8: U6.7 908.54,923.25 1351.5,923.25 1445,1016.76 v2@1445,1231 ; JP5.13 JP5.13@2208.66,1991.34
  Top Layer w10: JP5.14@2185.67,1914.33 JP5.14@2190,1918.66 ; JP5.13 JP5.14@2190,1918.66 ; R7.1@2272.05,1746.71 2272.05,1827.95 JP5.14 JP5.14@2190,1918.66
  Bottom Layer w8: v2(1444,1231) 1528,1315 2021.57,1315 2080,1373.43 2080,1685 2190,1795 JP5.14 JP5.13
P56: JP5.15 JP5.16 R8.1 U6.8 | length 2503.7
  Top Layer w8: U6.8 915.06,939 1337.24,939 1415,1016.76 v2@1415,1200
  Top Layer w10: R8.1@2002.05,1746.71 2002.05,1822.05 JP5.16 JP5.15
  Bottom Layer w8: v2@1415,1206 1415,1242 1484.85,1311.85 ; 1500,1327 1484.85,1311.85 ; JP5.15 JP5.16 2060,1880 2060,1381.72 2013.28,1335 1508,1335 1484.85,1311.85
  other v2: 1416,1206
P57: JP5.17 JP5.18 R9.1 U6.21 | length 2293.1
  Top Layer w8: U6.21 v2@929.46,1241.54
  Top Layer w10: R9.1@1732.05,1746.71 1732.05,1757.05 1825,1850 1930,1850 JP5.18 JP5.17
  Bottom Layer w8: v2(923,1248) 1368,1248 1475,1355 2005,1355 2040,1390 2040,1860 JP5.18 JP5.17
P60: C10.2 J6.35 J6.36 JP6.3 JP6.4 U6.41 X2.2 | length 3773.1
  Top Layer w8: U6.41 733.8,1120.26 939.74,1120.26 970,1090 1195,1090 v2(1205,1100) ; X2.2 X2.2@1790,523.42
  Bottom Layer w8: JP6.3@215,310 JP6.3 JP6.4 240,460 310,460 340,430 340,280 386,234 1529,234 1790,495 X2.2@1790,523.42 ; v2@1204,1090 1204,1078 1337,945 1655,945 J6.36 J6.35 X2.2@1790,523.42 ; X2.2 X2.2@1790,523.42
P61: C11.2 J6.37 J6.38 JP6.5 JP6.6 U6.40 X2.1 | length 3808.2
  Top Layer w8: U6.40 740.32,1136.01 953.99,1136.01 980,1110 1175,1110 1195,1130 1217,1130 v2@1222,1125 ; X2.1@1950,486.58 X2.1
  Bottom Layer w8: JP6.6 JP6.5 290,285 362,213 1538,213 1715,390 1853.43,390 X2.1 1950,523.42 1950,559.21 C11.2 1890,640.79 J6.37 1890,790 1715,965 1348,965 1237,1076 1237,1119 v2(1225,1131)
P62: JP6.7 JP6.8 U6.39 | length 1360.6
  Top Layer w8: v2(575,1287) 579,1291 607.6,1291 U6.39
  Bottom Layer w8: JP6.7 JP6.8 405,425 405,515 240,680 240,1097 448,1305 557,1305 v2(575,1287)
P63: JP6.9 JP6.10 U6.38 | length 1426.5
  Top Layer w8: v2@599.94,1320.94 U6.38
  Bottom Layer w8: JP6.9@490,285 JP6.9 JP6.10 490,600 440,650 440,830 414,856 347.13,856 280,923.13 280,1078 456.58,1254.58 581.58,1254.58 602,1275 v2@602,1316
  other v2: 595,1316
P64: JP6.11 JP6.12 U6.37 | length 1467.2
  Top Layer w8: v2@623.57,1319.57 U6.37
  Bottom Layer w8: JP6.11 JP6.12 540,460 540,829 494,875 355,875 299,931 299,1066.83 470.34,1238.17 592.17,1238.17 622,1268 v2@622,1325
  other v2: 629,1325
P65: JP6.13 JP6.14 U6.24 | length 1069.4
  Top Layer w8: v2(784,1203) 824.1,1203 U6.24
  Bottom Layer w8: JP6.13 JP6.14 641,459 641,841 747.71,947.71 747.71,1166.71 v2(784,1203)
P66: JP6.15 JP6.16 U6.23 | length 1013.4
  Top Layer w8: v2@780.5,1163.5 805,1188 831.37,1188 U6.23
  Bottom Layer w8: v2(782,1162) 767,1147 767,940 740,913 740,460 JP6.16 JP6.15
P67: JP6.17 JP6.18 U6.22 | length 1001
  Top Layer w8: v2@817,1164 829.64,1164 U6.22
  Bottom Layer w8: v2(817,1162) 817,1151 786,1120 786,895 840,841 840,460 JP6.18 JP6.17
P70: JP7.3 JP7.4 U6.46 | length 1108
  Top Layer w8: U6.46 499,1243.71 499,1294 473,1320 454,1320 414,1360 371,1360 340,1391 340,1575 JP7.4@690,1925 ; JP7.4 JP7.4@690,1925 ; JP7.3 JP7.4@690,1925
P71: JP7.5 JP7.6 U6.47 | length 1178.1
  Top Layer w8: U6.47 518.44,1202 517,1202 399,1320 360,1320 320,1360 260,1360 240,1380 240,1540 275,1575 300,1575 590,1865 JP7.6 JP7.5
P72: JP7.7 JP7.8 U6.48 | length 1303.8
  Top Layer w8: JP7.7 JP7.8 490,1805 285,1600 195,1600 140,1545 140,1390 170,1360 225,1360 245,1340 313.29,1340 352.18,1301.11 391.18,1301.11 509.18,1183.11 515.05,1183.11 U6.48
RST: C16.2 J6.17 J6.18 J14.6 R3.2 SW1.2 U6.33 | length 2234.9
  Top Layer w8: U6.33 715.31,1316.92 733.09,1316.92 v2@813,1237.01 ; J14.6 1145,465 1410,465 1440,435 1440,390 1485.05,344.95 1800.05,344.95 1820,325 R3.2@1820,280 ; SW1.2 1820,152.79 1820,258.66 ; R3.2@1836.34,275 C16.2@1945,275
  Bottom Layer w8: v2(813,1229) 845,1197 845,1153 804,1112 804,909 890,823 J6.18 J6.17 890,610 J14.6
SCL/P44: J5.3 J5.4 J14.2 U6.34 | length 3373.3
  Top Layer w8: J5.3@190,1385 J5.3 J5.4 ; v2(350,525) 385,490 1425,490 1490,425 J14.2 ; U6.34 669,1340.96 669,1354 679,1364 715,1364 741,1390 v2@741,1626
  Bottom Layer w8: J5.3 190,1350 140,1300 140,675 290,525 v2(350,525) ; J5.4 190,1548 305,1663 707,1663 v2(744,1626) ; J14.2@1510,410 J14.2@1510,415
SDA/P45: J5.5 J5.6 J14.4 U6.35 | length 3112.7
  Top Layer w8: J5.6 J5.5 295,1410 365,1340 405,1340 v2@472.5,1272.5 ; v2@640,1585 640,1347.69 U6.35
  Bottom Layer w8: J5.6 370,1590 v2@640,1590 ; v2@477,1277 449,1277 260,1088 260,914.85 340,834.85 340,670 440,570 440,285 470,255 1135,255 J14.4
  other v2: 474,1281 642,1585
VDD: C16.1 D4.1 D5.1 D6.1 D7.1 J2.1 J2.2 J2.3 J5.1 J5.2 J7.1 J14.3 JP4.1 JP4.2 JP5.1 JP5.2 JP6.1 JP6.2 JP7.1 JP7.2 R10.1 SW1.1 SW2.2 | length 9097.3
  Top Layer w8: 1360,70 1380,90 ; 1400,90 1420,70 ; 2770,1645 2790,1665 ; 2810,1665 2830,1645
  Top Layer w30: J5.2 75.09,1495.09 75.09,935.09 30,890 30,470 JP6.2 JP6.1 155,245 190,245 273.65,161.35 273.65,81.35 315,40 750,40 775,65 1390,65 ; JP7.1 JP7.2 790,1785 850,1725 1365,1725 1435,1655 1555.5,1655 D6.1 ; J14.3 1390,65 ; D6.1@1568,1665 D5.1@1802.29,1665 ; v6(1790,1640) 2220,1640 ; JP4.2 JP4.1 ; SW2.2 2240,1620 ; 2254.21,1634.21 2240,1620 ; J7.1 2480,325 2445,290 2059.21,290 C16.1 2054.21,168.58 SW1.1 2007.79,65 1390,65 ; JP5.2 JP5.1 ; JP5.2@2800,1915 2800,1640 ; J2.1 J2.2 3045.24,1640 ; J2.3 3045.24,1640 ; 2220,1640 2240,1620 ; 2220,1640 2240,1640 ; 2240,1620 2240,1640 ; 2240,1640 2800,1640 ; 2800,1640 3045.24,1640
  Bottom Layer w30: J5.2 283.27,1703.27 718.27,1703.27 790,1775 JP7.2 ; v6(1790,1640) JP4.2
VDD3: C8.1 J4.3 U2.1 | length 196.3
  Top Layer w30: C8.1@2410,1415.28 2418.66,1415.28 2418.66,1312.34 J4.3 ; C8.1@2430,1415.28 U2.1@2498.66,1415.28
VDD5: C1.1 C2.2 C5.1 C7.1 D1.2 J4.1 U2.3 U5.5 | length 1057.7
  Top Layer w30: U5.5 2275.63,993.66 C2.2@2300.63,1018.66 ; C2.2 2425.79,1020.79 2445,1040 2445,1219 2519,1219 2609.21,1309.21 C5.1@2633.66,1309.21 ; U2.3@2627.72,1412.17 U2.3@2633.66,1412.17 ; C5.1 C5.1@2633.66,1309.21 ; D1.2@2873.66,1418.12 2633.66,1418.12 U2.3@2633.66,1412.17 ; C5.1@2633.66,1309.21 U2.3@2633.66,1412.17
VREF+: J15.2 U6.57 | length 1666.5
  Top Layer w10: 585,980 601.1,980 U6.57@614.55,993.45
  Top Layer w12: v2(110,878) 129,878 246,995 570,995 585,980
  Bottom Layer w12: v2(110,878) 88,878 40,830 40,645 140,545 140,280 230,190 410,190 J15.2
pads on no net: J5.19 J5.20 J5.23 J5.24 J8.0 J14.1 J15.4 JP4.17 JP4.18 JP7.9 JP7.10 U5.1 U5.9 U5.10 U5.11 U5.12 U5.13 U5.14 U5.15 U5.16

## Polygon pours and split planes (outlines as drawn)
GND_POWER on Bottom Layer "Bottom Layer-No Net" (hatched 90Degree grid 10 track 10, remove dead copper, pour order 1001): 20,29 3080,29 3080,2080 20,2080
GND_POWER on Top Layer "Bottom Layer-No Net" (hatched 90Degree grid 10 track 10, remove dead copper, pour order 1001): 20,29 3080,29 3080,2080 20,2080

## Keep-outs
Keep-Out Layer:
  circle w10: c2985.24,115 r120
  circle w10: c120,1990 r120
  circle w10: c120,115 r100
  circle w10: c2985.24,1990 r120

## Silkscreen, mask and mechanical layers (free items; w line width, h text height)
Top Overlay:
  text "P41" at 1540,1815 h33
  text "P40" at 1640,1815 h33
  text "VDD" at 1740,1815 h33
  text "GND" at 1850,1815 h33
  text "P57" at 1950,1815 h33
  text "P56" at 2050,1815 h33
  text "P55" at 2150,1815 h33
  text "P54" at 2250,1815 h33
  text "P53" at 2350,1815 h33
  text "P52" at 2450,1815 h33
  text "P51" at 2550,1815 h33
  text "P50" at 2650,1815 h33
  text "VDD" at 2750,1815 h33
  text "P72" at 505,1765 h33 r90
  text "P71" at 600,1765 h33 r90
  text "P70" at 705,1765 h33 r90
  text "VDD" at 800,1765 h33 r90
  text "GND" at 905,1765 h33 r90
  text "P46" at 1100,1765 h33 r90
  text "P01" at 1205,1765 h33 r90
  text "P00" at 1300,1765 h33 r90
  text "P43" at 1410,1765 h33 r90
  text "P42" at 1500,1765 h33 r90
  text "GND" at 307,1760 h33 r90
  text "Power" at 2790,1640 h40
  text "Power Off" at 2160,1635 h40
  text "P02" at 410,1575 h38 r90
  text "P07" at 910,1575 h38 r90
  text "P06" at 812,1574 h38 r90
  text "P03" at 512.36,1573.36 h38 r90
  text "P44" at 210,1572 h40 r90
  text "P45" at 310,1572 h40 r90
  text "P04" at 611,1572 h38 r90
  text "VDD" at 109,1571 h40 r90
  text "P46" at 1110,1571 h38 r90
  text "P05" at 715,1570 h38 r90
  text "P27" at 1310,1570 h35 r90
  text "P26" at 1420,1570 h35 r90
  text "P25" at 1510,1570 h35 r90
  text "P24" at 1540,1570 h35
  text "P23" at 1650,1570 h35
  text "P22" at 1760,1570 h35
  text "P21" at 1865,1570 h35
  text "P20" at 1970,1570 h35
  text "VDD" at 3073.24,1320 h50 r90
  text "VDD3" at 2475,1290 h33
  text "VDD" at 2475,1240 h33
  text "MG82F6D64" at 980,1190 h45
  text "VDD5" at 2475,1190 h33
  text "Power On" at 2135,1180 h40
  text "GND" at 2790,1100 h33
  text "P31" at 1630,1090 h35
  text "D+" at 2790,1050 h33
  text "LQFP64_V10" at 981,1037.44 h45
  text "D-" at 2790,1010 h33
  text "P30" at 1630,1000 h35
  text "Ev Board" at 981,974.45 h45
  text "VDD" at 2790,960 h33
  text "TH210A" at 981,909.76 h45
  text "GND" at 3075.24,675 h50 r90
  text "P37" at 1640,615 h35
  text "P60" at 1750,615 h35
  text "P61" at 1860,615 h35.43
  text "GND" at 1960,615 h35.43
  text "P31" at 1110,565 h40 r90
  text "RST" at 910,555 h40 r90
  text "P30" at 1010,555 h40 r90
  text "P32" at 1212,555 h40 r90
  text "P33" at 1312,555 h40 r90
  text "P34" at 1412,555 h40 r90
  text "P35" at 1512,555 h40 r90
  text "P36" at 1612,555 h40 r90
  text "P15" at 603.95,551.95 h40 r90
  text "P16" at 703.95,551.95 h40 r90
  text "P17" at 803.95,551.95 h40 r90
  text "P10" at 110,545 h40 r90
  text "P11" at 200,545 h40 r90
  text "P12" at 300,545 h40 r90
  text "P13" at 410,545 h40 r90
  text "P14" at 510,545 h40 r90
  text "ISP" at 2335,510 h45
  text "ICE/ICP" at 1205,495 h45
  text "VDD" at 50,475 h33
  text "P60" at 150,475 h33
  text "P61" at 250,475 h33
  text "P62" at 350,475 h33
  text "P63" at 450,475 h33
  text "P64" at 550,475 h33
  text "P65" at 650,475 h33
  text "P66" at 750,475 h33
  text "P67" at 850,475 h33
  text "GND" at 950,475 h33
  text "RST" at 1060,445 h33
  text "GND" at 1155,445 h33
  text "SDA" at 1260,445 h33
  text "VDD" at 1360,445 h33
  text "SCL" at 1460,445 h33
  text "GND" at 2235,440 h33
  text "P31" at 2355,440 h33
  text "VDD" at 2460,440 h33
  text "VREF+" at 435,180 h50
  text "Reset" at 1850,20 h40
Mechanical 1:
  the board outline again, w13
Mechanical 2:
  circle w10: c2985.24,1990 r120
  circle w10: c120,115 r100
  circle w10: c120,1990 r120
  circle w10: c2985.24,115 r120

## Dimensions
0,0 to 3110.24,0 on Top Overlay
0,2110 to 0,0 on Top Overlay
